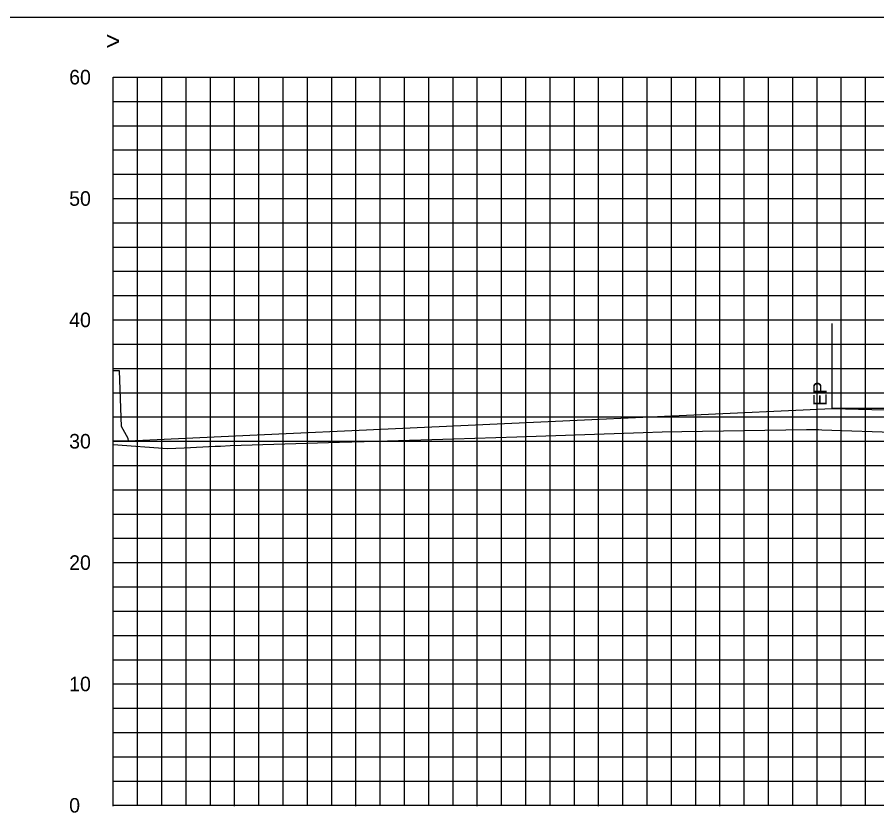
# Model space of a CAD drawing. Extents: x 2193008 to 2198143, y 1236112 to 1237864.
# Drawn here: x 2195380.9 to 2195451.7, y 1237162.5 to 1237228 of the extents above; entities that cross this region are included whole.
import ezdxf

# ---------------------------------------------------------------- set-up
doc = ezdxf.new("R2010")
doc.units = 0
for name, color, linetype in [('3', 7, 'Continuous'), ('31', 7, 'Continuous'), ('60', 7, 'Continuous'), ('Default', 7, 'Continuous'), ('GSDIMS', 7, 'Continuous'), ('Level 1', 7, 'Continuous'), ('Level 55', 7, 'Continuous'), ('M-ROADS', 7, 'Continuous')]:
    doc.layers.add(name, color=color, linetype=linetype)

msp = doc.modelspace()

# ---------------------------------------------------------------- linework, layer by layer
at = {"layer": '3'}
msp.add_line((2195448.033, 1237195.8), (2195448.033, 1237202.8), dxfattribs=at)
at = {"layer": '60'}
for p, q in [((2195388.783, 1237163.106), (2195388.783, 1237223.106)), ((2195388.783, 1237163.046), (2195388.783, 1237163.106)), ((2195388.783, 1237163.106), (2195518.783, 1237163.106)), ((2195398.783, 1237163.046), (2195398.783, 1237163.106)), ((2195408.783, 1237163.046), (2195408.783, 1237163.106)), ((2195418.783, 1237163.046), (2195418.783, 1237163.106)), ((2195428.783, 1237163.046), (2195428.783, 1237163.106)), ((2195438.783, 1237163.046), (2195438.783, 1237163.106)), ((2195448.783, 1237163.046), (2195448.783, 1237163.106))]:
    msp.add_line(p, q, dxfattribs=at)
msp.add_lwpolyline([(2195388.783, 1237193.146), (2195389.871, 1237193.142), (2195390.033, 1237193.15), (2195400.033, 1237193.607), (2195412.033, 1237194.155), (2195424.033, 1237194.703), (2195436.033, 1237195.252), (2195448.033, 1237195.8), (2195460.033, 1237195.509), (2195462.033, 1237195.46), (2195465.533, 1237195.32), (2195498.642, 1237184.284)], dxfattribs=at)
at = {"layer": 'Default'}
msp.add_lwpolyline([(2195388.783, 1237193.15), (2195390.033, 1237193.15), (2195390.014, 1237193.32), (2195389.463, 1237194.32), (2195389.283, 1237198.906), (2195388.783, 1237198.906)], dxfattribs=at)
at = {"layer": 'GSDIMS'}
msp.add_line((2195462.887, 1237195.8), (2195448.033, 1237195.8), dxfattribs=at)
at = {"layer": 'Level 1'}
msp.add_line((2195228.783, 1237228.046), (2195528.783, 1237228.046), dxfattribs=at)
at = {"layer": 'M-ROADS'}
for p, q in [((2195388.783, 1237223.106), (2195518.783, 1237223.106)), ((2195390.783, 1237163.106), (2195390.783, 1237223.106)), ((2195392.783, 1237163.106), (2195392.783, 1237223.106)), ((2195394.783, 1237163.106), (2195394.783, 1237223.106)), ((2195396.783, 1237163.106), (2195396.783, 1237223.106)), ((2195398.783, 1237163.106), (2195398.783, 1237223.106)), ((2195400.783, 1237163.106), (2195400.783, 1237223.106)), ((2195402.783, 1237163.106), (2195402.783, 1237223.106)), ((2195404.783, 1237163.106), (2195404.783, 1237223.106)), ((2195406.783, 1237163.106), (2195406.783, 1237223.106)), ((2195408.783, 1237163.106), (2195408.783, 1237223.106)), ((2195410.783, 1237163.106), (2195410.783, 1237223.106)), ((2195412.783, 1237163.106), (2195412.783, 1237223.106)), ((2195414.783, 1237163.106), (2195414.783, 1237223.106)), ((2195416.783, 1237163.106), (2195416.783, 1237223.106)), ((2195418.783, 1237163.106), (2195418.783, 1237223.106)), ((2195420.783, 1237163.106), (2195420.783, 1237223.106)), ((2195422.783, 1237163.106), (2195422.783, 1237223.106)), ((2195424.783, 1237163.106), (2195424.783, 1237223.106)), ((2195426.783, 1237163.106), (2195426.783, 1237223.106)), ((2195428.783, 1237163.106), (2195428.783, 1237223.106)), ((2195430.783, 1237163.106), (2195430.783, 1237223.106)), ((2195432.783, 1237163.106), (2195432.783, 1237223.106)), ((2195434.783, 1237163.106), (2195434.783, 1237223.106)), ((2195436.783, 1237163.106), (2195436.783, 1237223.106)), ((2195438.783, 1237163.106), (2195438.783, 1237223.106)), ((2195440.783, 1237163.106), (2195440.783, 1237223.106)), ((2195442.783, 1237163.106), (2195442.783, 1237223.106)), ((2195444.783, 1237163.106), (2195444.783, 1237223.106)), ((2195446.783, 1237163.106), (2195446.783, 1237223.106)), ((2195448.783, 1237163.106), (2195448.783, 1237223.106)), ((2195450.783, 1237163.106), (2195450.783, 1237223.106)), ((2195388.783, 1237221.106), (2195518.783, 1237221.106)), ((2195388.783, 1237219.106), (2195518.783, 1237219.106)), ((2195388.783, 1237217.106), (2195518.783, 1237217.106)), ((2195388.783, 1237215.106), (2195518.783, 1237215.106)), ((2195388.783, 1237213.106), (2195518.783, 1237213.106)), ((2195388.783, 1237211.106), (2195518.783, 1237211.106)), ((2195388.783, 1237209.106), (2195518.783, 1237209.106)), ((2195388.783, 1237207.106), (2195518.783, 1237207.106)), ((2195388.783, 1237205.106), (2195518.783, 1237205.106)), ((2195388.783, 1237203.106), (2195518.783, 1237203.106)), ((2195388.783, 1237201.106), (2195518.783, 1237201.106)), ((2195388.783, 1237199.106), (2195518.783, 1237199.106)), ((2195388.783, 1237197.106), (2195518.783, 1237197.106)), ((2195388.783, 1237195.106), (2195518.783, 1237195.106)), ((2195388.783, 1237193.106), (2195518.783, 1237193.106)), ((2195388.783, 1237191.106), (2195518.783, 1237191.106)), ((2195388.783, 1237189.106), (2195518.783, 1237189.106)), ((2195388.783, 1237187.106), (2195518.783, 1237187.106)), ((2195388.783, 1237185.106), (2195518.783, 1237185.106)), ((2195388.783, 1237183.106), (2195518.783, 1237183.106)), ((2195388.783, 1237181.106), (2195518.783, 1237181.106)), ((2195388.783, 1237179.106), (2195518.783, 1237179.106)), ((2195388.783, 1237177.106), (2195518.783, 1237177.106)), ((2195388.783, 1237175.106), (2195518.783, 1237175.106)), ((2195388.783, 1237173.106), (2195518.783, 1237173.106)), ((2195388.783, 1237171.106), (2195518.783, 1237171.106)), ((2195388.783, 1237169.106), (2195518.783, 1237169.106)), ((2195388.783, 1237167.106), (2195518.783, 1237167.106)), ((2195388.783, 1237165.106), (2195518.783, 1237165.106)), ((2195388.783, 1237163.106), (2195518.783, 1237163.106))]:
    msp.add_line(p, q, dxfattribs=at)
msp.add_lwpolyline([(2195388.783, 1237192.848), (2195393.265, 1237192.507), (2195394.616, 1237192.569), (2195397.175, 1237192.694), (2195397.611, 1237192.711), (2195398.426, 1237192.75), (2195407.416, 1237193.023), (2195410.473, 1237193.115), (2195416.845, 1237193.31), (2195422.03, 1237193.474), (2195432.448, 1237193.839), (2195434.033, 1237193.89), (2195435.65, 1237193.918), (2195445.928, 1237194.08), (2195446.918, 1237194.064), (2195447.18, 1237194.058), (2195453.801, 1237193.813)], dxfattribs=at)

# ---------------------------------------------------------------- texts
at = {"layer": '31'}
for s, p in [('60', (2195385.15, 1237222.506)), ('50', (2195385.15, 1237212.506)), ('40', (2195385.15, 1237202.506)), ('30', (2195385.15, 1237192.506)), ('20', (2195385.15, 1237182.506)), ('10', (2195385.15, 1237172.506)), ('0', (2195385.15, 1237162.506))]:
    msp.add_text(s, height=1.2, dxfattribs=at).set_placement(p)
at = {"layer": '60'}
msp.add_text('>', height=1.5, dxfattribs=at).set_placement((2195388.175, 1237225.356))
at = {"layer": 'Level 55'}
msp.add_text('EP', height=1.1105, rotation=90, dxfattribs=at).set_placement((2195447.581, 1237196.032))

doc.saveas('drawing.dxf')
